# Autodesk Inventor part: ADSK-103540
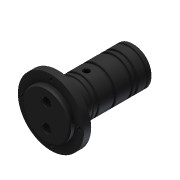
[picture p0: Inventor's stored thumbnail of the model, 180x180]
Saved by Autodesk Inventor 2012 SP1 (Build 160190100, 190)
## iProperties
Shininess: 20.0
Created: 2001-04
Part Number: ADSK-103540
Document SubType Name: Modeling
Designer: Administrator
Stock Number: ADSK-103540
Density: 1 g/cm^3
Material: Default
Density: 0.0
Volumn: 0.0
Area: 0.0
PropertySet Name: Model Information
Control State: 0
Master: False
Checked Out: False
Author: Administrator
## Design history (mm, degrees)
sketch "Sketch1"
  geometry: C1 r 44.45 at (0, 0)
  constraints: 1 centre point
  dimensions: "d0" = 88.9 diameter of C1
extrude "Extrusion1" new body sketch "Sketch1" distance "d1" = 9.525; taper "d2" = 0 deg
sketch "Sketch2"
  geometry: C1 r 44.45 at (0, 0) reference; C2 r 31.75 at (0, 0)
  constraints: 1 centre point
  dimensions: "d3" = 63.5 diameter of C2
extrude "Extrusion2" join sketch "Sketch2" distance "d4" = 6.35; taper "d5" = 0 deg
sketch "Sketch3"
  geometry: C1 r 44.45 at (0, 0) reference; C2 r 25.298 at (0, 0)
  constraints: 1 centre point
  dimensions: "d6" = 50.5968 diameter of C2
extrude "Extrusion3" join sketch "Sketch3" distance "d7" = 101.6; taper "d8" = 0 deg
chamfer "Chamfer1" distance "d9" = 1.5875; stored, may be unused: second distance "d10" = 1.5875, angle "d77" = 45 deg
chamfer "Chamfer2" distance "d11" = 1.5875; stored, may be unused: second distance "d12" = 1.5875, angle "d78" = 45 deg
sketch "Sketch4"
  geometry: C1 r 1.841 at (0, 38.1) reference; C2 r 1.841 at (-38.1, 0) reference; C3 r 1.841 at (0, -38.1) reference; C4 r 1.841 at (38.1, 0) reference; 4 further points
  constraints: 4 coincident
hole "Hole1" sketch "Sketch4" at (0, 38.1), (-38.1, 0), (0, -38.1), (38.1, 0) diameter "d13" = 5.55625; stored, may be unused: countersink angle "d17" = 60 deg, drill point angle "d19" = 118 deg; dims "d14" = 12.7, "d15" = 9.525, "d16" = 6.35, "d18" = 19.05
workplane "Work Plane1"
workaxis "Work Axis1"
workplane "Work Plane2"
sketch "Sketch5"
  geometry: L1 (0, 39.37)-(0, -125.095) reference; L2 (-44.45, 0)-(44.45, 0) reference; 1 further point
  constraints: 1 point on line
  dimensions: "d20" = 38.1 distance from line of L2 point (0, -38.1)
hole "Hole2" sketch "Sketch5" at (0, -38.1) diameter "d21" = 7.9375; stored, may be unused: countersink angle "d25" = 60 deg, drill point angle "d27" = 118 deg; dims "d22" = 12.7, "d23" = 9.525, "d24" = 6.35, "d26" = 19.05
sketch "Sketch6"
  geometry: L1 (0, 39.37)-(0, -125.095) reference; L2 (-44.45, 0)-(44.45, 0) reference; 1 further point
  constraints: 1 point on line
  dimensions: "d28" = 63.5 distance from line of L2 point (0, -63.5)
hole "Hole3" sketch "Sketch6" at (0, -63.5) diameter "d29" = 7.9375; stored, may be unused: countersink angle "d33" = 60 deg, drill point angle "d35" = 118 deg; dims "d30" = 12.7, "d31" = 9.525, "d32" = 6.35, "d34" = 19.05
sketch "Sketch7"
  geometry: L1 (0, 0)-(0, 30.162); L2 (0, 0)-(0, -30.162); A1 r 30.162 centre (0, 0) between (0, 30.162) and (0, -30.162) reference; 1 further point
  constraints: 4 end point, 2 point on circle, 1 collinear, 1 midpoint, 1 vertical
hole "Hole4" sketch "Sketch7" at (0, 15.081) diameter "d36" = 7.9375; stored, may be unused: countersink angle "d40" = 60 deg, drill point angle "d42" = 118 deg; dims "d37" = 12.7, "d38" = 12.7, "d39" = 12.7, "d41" = 63.5
sketch "Sketch8"
  geometry: L1 (0, 0)-(0, -30.162); 1 further point
  constraints: 2 end point, 1 midpoint, 1 vertical, 1 vertical alignment, 1 other
hole "Hole5" sketch "Sketch8" at (0, -15.081) diameter "d43" = 7.9375; stored, may be unused: countersink angle "d47" = 60 deg, drill point angle "d49" = 118 deg; dims "d44" = 12.7, "d45" = 12.7, "d46" = 12.7, "d48" = 88.9
sketch "Sketch9"
  geometry: C1 r 25.298 at (0, 0) reference; C2 r 31.75 at (0, 0)
  constraints: 1 centre point
  dimensions: "d50" = 63.5 diameter of C2
extrude "Extrusion4" join sketch "Sketch9" distance "d51" = 8.255; taper "d52" = 0 deg
fillet "Fillet1" dims "d53" = 0.79375
workplane "Work Plane3"
sketch "Sketch10"
  geometry: C1 r 25.298 at (0, 0) reference; C2 r 23.876 at (0, 0)
  constraints: 1 centre point
  dimensions: "d56" = 47.752 diameter of C2
extrude "Extrusion5" cut sketch "Sketch10" distance "d57" = 1.7272; taper "d58" = 0 deg
thread "Thread1" dims "d59" = 25.4, "d60" = 0
thread "Thread2" dims "d61" = 25.4, "d62" = 0
workplane "Work Plane4"
sketch "Sketch11"
  geometry: C1 r 25.298 at (0, 0) reference; C2 r 23.368 at (0, 0)
  constraints: 1 centre point
  dimensions: "d64" = 46.736 diameter of C2
extrude "Extrusion6" cut sketch "Sketch11" distance "d65" = 3.556; taper "d66" = 0 deg
pattern_linear "Rectangular Pattern1" dims "d70" = 7.112
pattern_linear "Rectangular Pattern2" dims "d73" = 52.578
pattern_linear "Rectangular Pattern3" dims "d76" = 29.845
body "Solid1"
other parameters: "d54" = -6.35, "d63" = 10.795
